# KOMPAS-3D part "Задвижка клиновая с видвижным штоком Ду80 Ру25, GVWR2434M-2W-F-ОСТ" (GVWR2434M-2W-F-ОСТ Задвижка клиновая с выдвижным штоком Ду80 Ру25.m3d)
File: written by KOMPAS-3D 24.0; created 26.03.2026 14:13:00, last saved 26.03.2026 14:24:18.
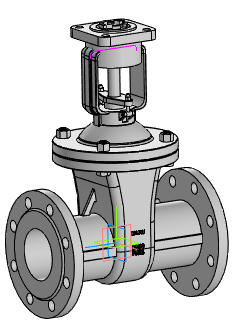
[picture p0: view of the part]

Document properties: Автор: R2D2; Полное имя файла: E:\Работа\Зайцев\GVWR2434M-2W-F-ОСТ Задвижка клиновая с выдвижным штоком DN.ru Ду50-300 Ру25\исходные материалы\DN80\GVWR2434M-2W-F-ОСТ Задвижка клиновая с выдвижным штоком Ду80 Ру25.m3d

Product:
- Component [detail]: AS 1110 - M12 x 45  | qty 4  | pos. 2  | Комментарий: Болты и винты   шестигранные точные   метрические ISO; Автор: R2D2; additional columns: Сталь, мягкая; source file: AS 1110 - M12 x 45 AS 1110 - M12 x 45.m3d
- Component [detail]: ANSI B18.2.4.2M - M12x1,75 - 18  | designation ANSI B18.2.4.2M - M12x1,75  | qty 4  | pos. 3  | Комментарий: Типы метрических   шестигранных гаек   2; Автор: R2D2; additional columns: Сталь, мягкая; source file: ANSI B18.2.4.2M - M12x1,75 ANSI B18.2.4.2M - M12x1,75 - 18.m3d
- Component [detail]: ANSI B18.2.4.2M - M5x0,8 - 8  | designation ANSI B18.2.4.2M - M5x0,8  | qty 2  | pos. 4  | Комментарий: Типы метрических   шестигранных гаек   2; Автор: R2D2; additional columns: Сталь, мягкая; source file: ANSI B18.2.4.2M - M5x0,8 ANSI B18.2.4.2M - M5x0,8 - 8.m3d
- Component [detail]: Деталь1  | qty 1  | pos. 5  | additional columns: Типовые; source file: 2.m3d
- Component [detail]: Фланец  | qty 2  | pos. 5  | Автор: R2D2; additional columns: Типовые; source file: Фланец DN80 PN25 b20.m3d
- Component [assembly]: DN50_3D_STEP  | designation Сборка  | qty 1  | pos. 6  | Масса: 2.725126; Автор: R2D2; source file: Фланец А.a3d
- Part/product: Задвижка клиновая с видвижным штоком Ду80 Ру25  | designation GVWR2434M-2W-F-ОСТ
    Масса: 24
    Раздел спецификации: Прочие изделия
    Примечание: D040-07587

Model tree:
1. Массив по концентрической сетке:1  (labels: Грань.Твердое тело1)  (4 pattern instances)
     Шаг 2 = 360
2. Массив по концентрической сетке:2  (labels: Грань.Твердое тело1)  (2 pattern instances)
     Шаг 2 = 360
3. Элемент выдавливания:3  (with: Грань.Элемент выдавливания:2, Грань.Элемент вращения:1)
     Расстояние 1 = 44.7058
4. Элемент выдавливания:4  (with: Грань.Элемент выдавливания:3, Грань.Элемент вращения:1)
     Расстояние 1 = 39.7507
5. Элемент выдавливания:5  (with: Грань.Элемент выдавливания:3)
     Расстояние 1 = 10
6. Эскиз:2  (with: Вершина.Элемент выдавливания:5, Ребро.Элемент выдавливания:3)
7. Элемент по траектории:1  (with: Грань.Элемент выдавливания:5)
     Толщина стенки 1 = 1; Длина траектории = 97.708
8. Элемент выдавливания:6  (with: Грань.Элемент выдавливания:5)
9. Эскиз:3  (with: Ребро.Элемент выдавливания:4, Ребро.Элемент выдавливания:3)
10. Элемент вращения:1
     Угол 1 = 360
11. Фаска:1  (with: Ребро.Элемент вращения:1)
     Угол = 45; Длина 1 = 3; Длина 2 = 3
12. Эскиз:4
13. Элемент выдавливания:7  (with: Грань.Элемент выдавливания:3, Грань.Элемент вращения:1, Грань.Операция без истории:2, Грань.Элемент выдавливания:5)  (labels: Грань.Твердое тело1; Грань.Solid1; Solid1; Твердое тело1)
     Расстояние 1 = 61; Смещение 1 = 1; Расстояние = -140; Ориентация = 2; Расстояние = -340

Expressions: 135+6
Referenced files in E:\Работа\Зайцев\GVWR2434M-2W-F-ОСТ Задвижка клиновая с выдвижным штоком DN.ru Ду50-300 Ру25\исходные материалы\DN80\: AS 1110 - M12 x 45 AS 1110 - M12 x 45.m3d, ANSI B18.2.4.2M - M12x1,75 ANSI B18.2.4.2M - M12x1,75 - 18.m3d, ANSI B18.2.4.2M - M5x0,8 ANSI B18.2.4.2M - M5x0,8 - 8.m3d, 2.m3d, Фланец А.a3d, Фланец DN80 PN25 b20.m3d
Referenced files in E:\Работа\Зайцев\GVWR3131M-2W-F-S Задвижка клиновая с выдвижным штоком DN.ru Ду50-200 Ру63\DN80\исходные материалы\: ANSI B18.2.4.2M - M12x1,75 ANSI B18.2.4.2M - M12x1,75 - 18.m3d, AS 1110 - M12 x 45 AS 1110 - M12 x 45.m3d, ANSI B18.2.4.2M - M5x0,8 ANSI B18.2.4.2M - M5x0,8 - 8.m3d
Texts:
  GVWR2434M-2W-F-ОСТ
  DN80
  GOST 26.020 Pr3
  PN25
  AS 1110 - M12 x 45 AS 1110 - M12 x 45 (1)
  ANSI B18.2.4.2M - M12x1,75 ANSI B18.2.4.2M - M12x1,75 - 18 (1)
  ANSI B18.2.4.2M - M5x0,8 ANSI B18.2.4.2M - M5x0,8 - 8 (1)
  Деталь1 Деталь1
  Фланец (1)
  Фланец (2)
  ANSI B18.2.4.2M - M12x1,75 ANSI B18.2.4.2M - M12x1,75 - 18 (2)
  AS 1110 - M12 x 45 AS 1110 - M12 x 45 (2)
  ANSI B18.2.4.2M - M12x1,75 ANSI B18.2.4.2M - M12x1,75 - 18 (3)
  AS 1110 - M12 x 45 AS 1110 - M12 x 45 (3)
  ANSI B18.2.4.2M - M12x1,75 ANSI B18.2.4.2M - M12x1,75 - 18 (4)
  AS 1110 - M12 x 45 AS 1110 - M12 x 45 (4)
  ANSI B18.2.4.2M - M5x0,8 ANSI B18.2.4.2M - M5x0,8 - 8 (2)
  Сборка DN50_3D_STEP
  Ось Y.Начало координат
  Ось Z.Начало координат
  Плоскость ZX.Начало координат
  Плоскость XY.Начало координат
